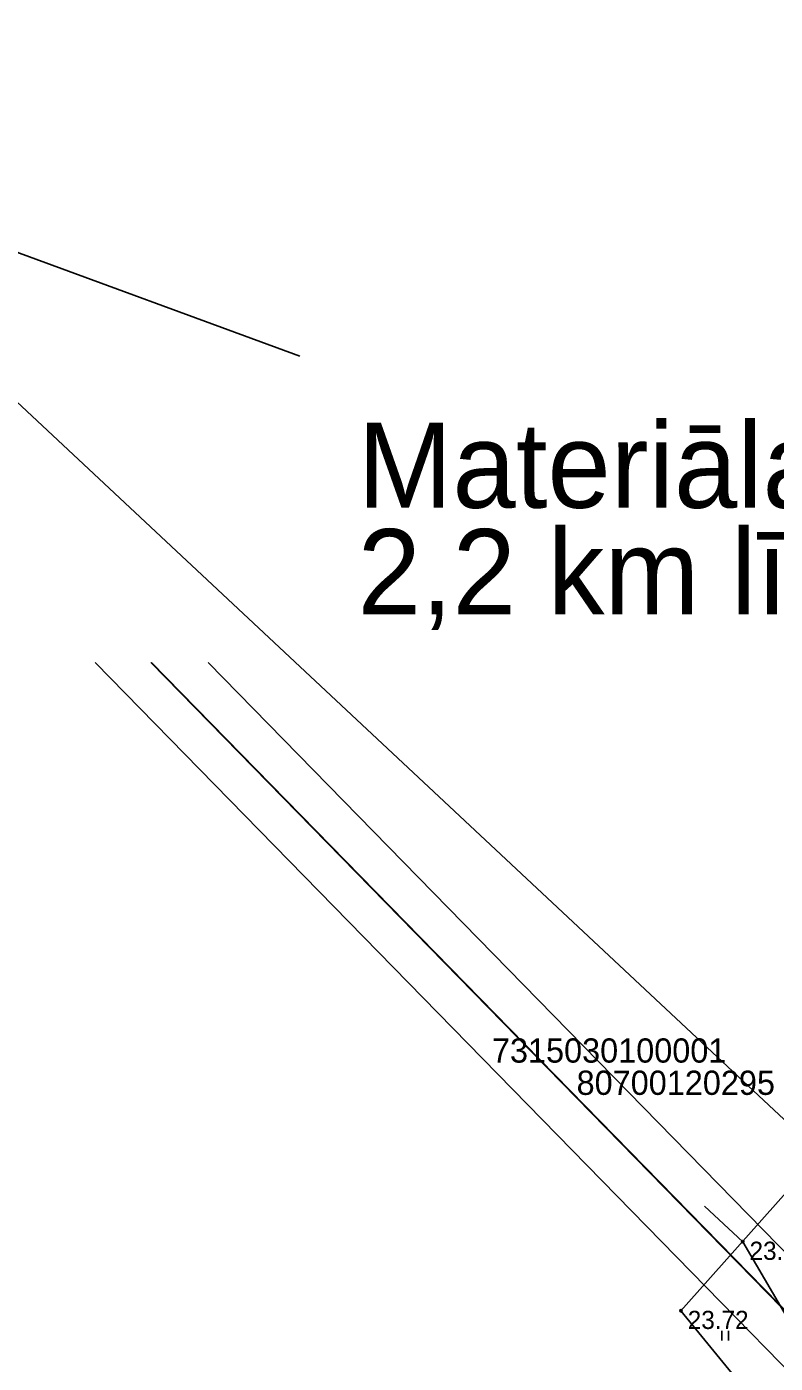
# Model space of a CAD drawing. Extents: x 521824 to 524158, y 294774 to 296228.
# Drawn here: x 521975 to 522021.3, y 296028.6 to 296111.3 of the extents above; entities that cross this region are included whole.
import ezdxf

# ---------------------------------------------------------------- set-up
doc = ezdxf.new("R2010")
doc.units = 0
for name, color, linetype in [('7315030100', 7, 'Continuous'), ('7315030100_TEXT', 7, 'Continuous'), ('CELI_CMAL_####_####_#', 7, 'Continuous'), ('Geolite Projekts', 7, 'Continuous'), ('RAMI_UZMR_####_####_#', 7, 'Continuous'), ('RELJ_AATZ_####_TKST_#', 7, 'Continuous'), ('RELJ_ELEM_####_####_#', 7, 'Continuous'), ('ROBZ_IERR_####_####_#', 7, 'Continuous'), ('ROBZ_PROJ_####_####_#', 7, 'Continuous'), ('ROBZ_PROJ_####_TKST_#', 7, 'Continuous'), ('ROBZ_UZMR_####_####_#', 7, 'Continuous'), ('TERT_ELEM_####_####_#', 7, 'Continuous')]:
    doc.layers.add(name, color=color, linetype=linetype)

msp = doc.modelspace()

# ---------------------------------------------------------------- linework, layer by layer
at = {"layer": '7315030100'}
msp.add_lwpolyline([(521982.662, 296071.944), (522030.784, 296022.739), (522033.541, 296023.509), (522041.383, 296002.911), (522075.382, 295945.049), (522118.888, 295885.85), (522163.663, 295827.44), (522159.464, 295824.698), (522114.889, 295882.848), (522071.201, 295942.295), (522036.863, 296000.733), (522028.996, 296021.046), (521979.248, 296071.92), (521979.226, 296071.945)], dxfattribs=at)
at = {"layer": 'CELI_CMAL_####_####_#'}
msp.add_lwpolyline([(522016.926, 296038.306), (522019.291, 296036.109), (522026.144, 296024.408), (522024.611, 296016.559), (522016.21, 296007.977), (522009.446, 296002.958), (521998.646, 295996.811), (521986.577, 295992.078), (521974.364, 295987.793), (521962.15, 295983.065), (521949.049, 295978.089), (521936.439, 295973.322), (521922.423, 295968.209), (521916.609, 295966.986)], dxfattribs=at)
at = {"layer": 'Geolite Projekts'}
msp.add_line((521958.082, 296103.28), (521991.894, 296090.895), dxfattribs=at)
msp.add_lwpolyline([(522051.641, 295994.078), (522023.126, 296042.473), (521958.082, 296103.28)], dxfattribs=at)
at = {"layer": 'RAMI_UZMR_####_####_#'}
msp.add_lwpolyline([(522023.729, 296021.723), (522015.468, 296031.834), (522031.173, 296049.489), (522037.438, 296043.035), (522045.257, 296040.016), (522064.856, 296037.774), (522081.006, 296041.17), (522170.455, 296046.167), (522192.824, 296044.95), (522215.986, 296046.637), (522238.336, 296053.36), (522285.718, 296059.481)], dxfattribs=at)
at = {"layer": 'RELJ_ELEM_####_####_#'}
for centre in [(522019.291, 296036.109), (522015.468, 296031.834)]:
    msp.add_circle(centre, 0.075, dxfattribs=at)
at = {"layer": 'ROBZ_IERR_####_####_#'}
msp.add_lwpolyline([(521982.721, 296071.944), (522030.783, 296022.794), (522033.554, 296023.535), (522231.747, 296043.148), (522293.95, 296059.25), (522300.416, 296060.924), (522337.144, 296010.443), (522362.112, 295976.434), (522359.108, 295971.285), (522349.756, 295955.259), (522172.848, 295833.392), (522168.097, 295830.304), (522159.466, 295824.695), (522157.572, 295823.464), (522100.03, 295786.069), (522037.633, 295748.407), (521945.66, 295684.513), (521914.938, 295661.444)], dxfattribs=at)
at = {"layer": 'ROBZ_PROJ_####_####_#'}
msp.add_lwpolyline([(521986.218, 296071.944), (522033.554, 296023.535), (522030.783, 296022.794), (521982.721, 296071.944)], dxfattribs=at)
at = {"layer": 'ROBZ_UZMR_####_####_#'}
msp.add_lwpolyline([(522148.908, 296111.268), (522231.747, 296043.148), (522033.554, 296023.535), (521986.218, 296071.944)], dxfattribs=at)
at = {"layer": 'TERT_ELEM_####_####_#'}
for p, q in [((522018, 296030), (522018, 296030.6)), ((522018.4, 296030), (522018.4, 296030.6))]:
    msp.add_line(p, q, dxfattribs=at)

# ---------------------------------------------------------------- texts
at = {"layer": '7315030100_TEXT'}
msp.add_text('7315030100001', height=1.5, dxfattribs=at).set_placement((522003.772, 296047.186))
at = {"layer": 'Geolite Projekts'}
for s, p in [('Materiāla izvešana', (521995.463, 296081.507)), ('2,2 km līdz P85', (521995.463, 296074.923))]:
    msp.add_text(s, height=5.26793, dxfattribs=at).set_placement(p)
at = {"layer": 'RELJ_AATZ_####_TKST_#'}
for s, p in [(' 23.70', (522019.291, 296034.984)), (' 23.72', (522015.468, 296030.709))]:
    msp.add_text(s, height=1.125, dxfattribs=at).set_placement(p)
at = {"layer": 'ROBZ_PROJ_####_TKST_#'}
msp.add_text('80700120295', height=1.5, dxfattribs=at).set_placement((522009.01, 296045.191))

doc.saveas('drawing.dxf')
